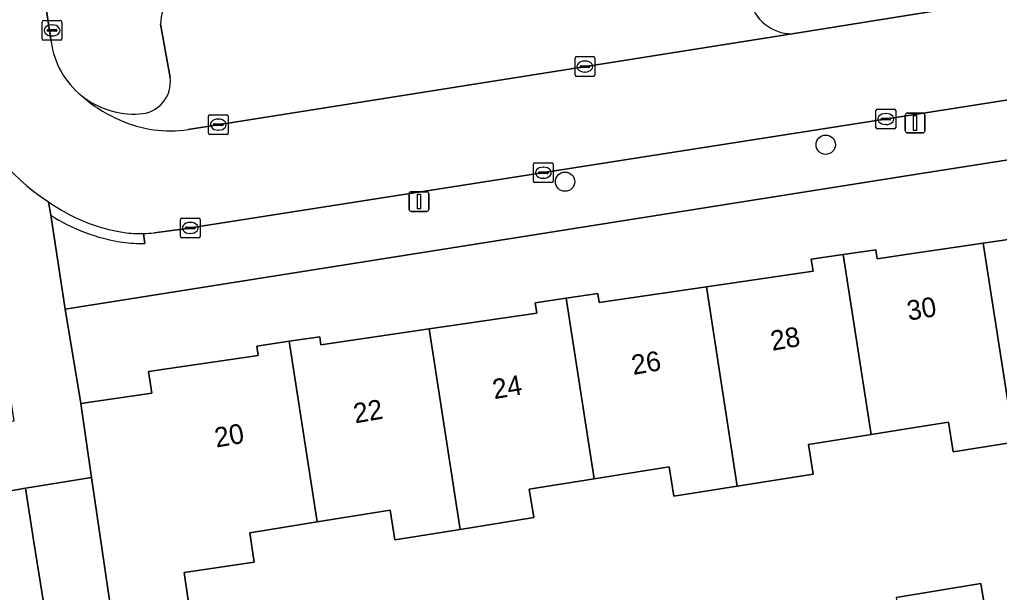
# Model space of a CAD drawing. Extents: x 160077 to 160948, y 386481 to 387498.
# Drawn here: x 160454.67 to 160504.27, y 387114.56 to 387143.58 of the extents above; entities that cross this region are included whole.
import ezdxf

# ---------------------------------------------------------------- set-up
doc = ezdxf.new("R2010")
doc.units = 0
for name, color, linetype in [('IMGEO_Boom', 7, 'Continuous'), ('IMGEO_Erf', 7, 'Continuous'), ('IMGEO_Kolk', 7, 'Continuous'), ('IMGEO_Lichtmast', 7, 'Continuous'), ('IMGEO_Muur', 7, 'Continuous'), ('IMGEO_Pand', 7, 'Continuous'), ('IMGEO_Pand_nummerreeks', 7, 'Continuous'), ('IMGEO_Parkeervlak_open', 7, 'Continuous'), ('IMGEO_Rijbaan_lokaal_open', 7, 'Continuous'), ('IMGEO_Voetpad_open', 7, 'Continuous')]:
    doc.layers.add(name, color=color, linetype=linetype)

msp = doc.modelspace()

# ---------------------------------------------------------------- linework, layer by layer
at = {"layer": 'IMGEO_Boom'}
for centre in [(160495.479, 387137.244), (160482.283, 387135.372)]:
    msp.add_circle(centre, 0.489, dxfattribs=at)
at = {"layer": 'IMGEO_Erf'}
for points in [[(160518.16, 387138.589), (160500, 387135.737), (160456.983, 387128.917), (160457.765, 387124.128), (160461.361, 387124.657), (160461.2, 387125.75), (160466.747, 387126.567), (160466.677, 387127.042), (160468.321, 387127.284), (160469.866, 387127.512), (160469.926, 387127.104), (160475.405, 387127.91), (160480.851, 387128.712), (160480.774, 387129.24), (160482.346, 387129.471), (160483.941, 387129.706), (160484.009, 387129.244), (160489.438, 387130.043), (160494.84, 387130.838), (160494.751, 387131.443), (160496.365, 387131.68), (160498.02, 387131.924), (160498.088, 387131.461), (160500, 387131.742), (160503.459, 387132.251), (160508.876, 387133.049)], [(160505.014, 387122.181), (160501.937, 387121.69), (160501.699, 387123.182), (160500, 387122.911), (160497.775, 387122.556), (160494.608, 387122.05), (160494.847, 387120.56), (160490.998, 387119.945), (160487.795, 387119.434), (160487.557, 387120.926), (160483.758, 387120.32), (160480.475, 387119.796), (160480.707, 387118.354), (160476.973, 387117.758), (160473.676, 387117.232), (160473.438, 387118.724), (160469.734, 387118.133), (160466.327, 387117.589), (160466.547, 387116.089), (160463.009, 387115.568), (160463.214, 387114.174)], [(160459.314, 387113.6), (160458.316, 387120.383), (160454.971, 387119.846), (160455.401, 387117.108), (160456.412, 387110.822)], [(160499.05, 387114.307), (160503.326, 387115.01), (160503.714, 387112.651)]]:
    msp.add_lwpolyline(points, dxfattribs=at)
at = {"layer": 'IMGEO_Kolk'}
for p, q in [((160455.816, 387142.609), (160455.816, 387143.461)), ((160455.891, 387143.535), (160456.743, 387143.535)), ((160456.817, 387143.461), (160456.817, 387142.609)), ((160456.075, 387143.029), (160456.075, 387143.041)), ((160456.513, 387142.992), (160456.115, 387142.992)), ((160456.118, 387143.078), (160456.516, 387143.078)), ((160456.304, 387143.315), (160456.329, 387143.315)), ((160456.559, 387143.041), (160456.559, 387143.029)), ((160456.743, 387142.535), (160455.891, 387142.535)), ((160456.327, 387142.755), (160456.302, 387142.755)), ((160482.789, 387140.78), (160482.789, 387141.632)), ((160482.864, 387141.706), (160483.716, 387141.706)), ((160483.277, 387141.486), (160483.302, 387141.486)), ((160483.79, 387141.632), (160483.79, 387140.78)), ((160483.048, 387141.2), (160483.048, 387141.212)), ((160483.486, 387141.163), (160483.088, 387141.163)), ((160483.091, 387141.249), (160483.489, 387141.249)), ((160483.3, 387140.926), (160483.275, 387140.926)), ((160483.532, 387141.212), (160483.532, 387141.2)), ((160483.716, 387140.706), (160482.864, 387140.706)), ((160498.024, 387138.121), (160498.024, 387138.973)), ((160498.099, 387139.047), (160498.951, 387139.047)), ((160499.025, 387138.973), (160499.025, 387138.121)), ((160464.231, 387137.838), (160464.231, 387138.69)), ((160464.306, 387138.764), (160465.158, 387138.764)), ((160464.719, 387138.544), (160464.744, 387138.544)), ((160465.232, 387138.69), (160465.232, 387137.838)), ((160498.283, 387138.541), (160498.283, 387138.553)), ((160498.721, 387138.504), (160498.323, 387138.504)), ((160498.326, 387138.59), (160498.724, 387138.59)), ((160498.512, 387138.827), (160498.537, 387138.827)), ((160498.767, 387138.553), (160498.767, 387138.541)), ((160464.49, 387138.258), (160464.49, 387138.27)), ((160464.928, 387138.221), (160464.53, 387138.221)), ((160464.533, 387138.307), (160464.931, 387138.307)), ((160464.742, 387137.984), (160464.717, 387137.984)), ((160464.974, 387138.27), (160464.974, 387138.258)), ((160498.951, 387138.047), (160498.099, 387138.047)), ((160498.535, 387138.267), (160498.51, 387138.267)), ((160465.158, 387137.764), (160464.306, 387137.764)), ((160480.685, 387135.4), (160480.685, 387136.252)), ((160480.76, 387136.326), (160481.612, 387136.326)), ((160481.173, 387136.106), (160481.198, 387136.106)), ((160481.686, 387136.252), (160481.686, 387135.4)), ((160480.944, 387135.82), (160480.944, 387135.832)), ((160481.382, 387135.783), (160480.984, 387135.783)), ((160480.987, 387135.869), (160481.385, 387135.869)), ((160481.196, 387135.546), (160481.171, 387135.546)), ((160481.428, 387135.832), (160481.428, 387135.82)), ((160481.612, 387135.326), (160480.76, 387135.326)), ((160462.886, 387133.528), (160463.738, 387133.528)), ((160462.811, 387132.602), (160462.811, 387133.454)), ((160463.07, 387133.022), (160463.07, 387133.034)), ((160463.508, 387132.985), (160463.11, 387132.985)), ((160463.113, 387133.071), (160463.511, 387133.071)), ((160463.299, 387133.308), (160463.324, 387133.308)), ((160463.554, 387133.034), (160463.554, 387133.022)), ((160463.812, 387133.454), (160463.812, 387132.602)), ((160463.738, 387132.528), (160462.886, 387132.528)), ((160463.322, 387132.748), (160463.297, 387132.748))]:
    msp.add_line(p, q, dxfattribs=at)
for points in [[(160455.816, 387142.609), (160455.816, 387143.461)], [(160455.891, 387143.535), (160456.743, 387143.535)], [(160456.817, 387143.461), (160456.817, 387142.609)], [(160456.743, 387142.535), (160455.891, 387142.535)], [(160482.789, 387140.78), (160482.789, 387141.632)], [(160482.864, 387141.706), (160483.716, 387141.706)], [(160483.79, 387141.632), (160483.79, 387140.78)], [(160483.716, 387140.706), (160482.864, 387140.706)], [(160498.024, 387138.121), (160498.024, 387138.973)], [(160498.099, 387139.047), (160498.951, 387139.047)], [(160499.025, 387138.973), (160499.025, 387138.121)], [(160464.231, 387137.838), (160464.231, 387138.69)], [(160464.306, 387138.764), (160465.158, 387138.764)], [(160465.232, 387138.69), (160465.232, 387137.838)], [(160498.951, 387138.047), (160498.099, 387138.047)], [(160465.158, 387137.764), (160464.306, 387137.764)], [(160480.685, 387135.4), (160480.685, 387136.252)], [(160480.76, 387136.326), (160481.612, 387136.326)], [(160481.686, 387136.252), (160481.686, 387135.4)], [(160481.612, 387135.326), (160480.76, 387135.326)], [(160462.886, 387133.528), (160463.738, 387133.528)], [(160462.811, 387132.602), (160462.811, 387133.454)], [(160463.812, 387133.454), (160463.812, 387132.602)], [(160463.738, 387132.528), (160462.886, 387132.528)]]:
    msp.add_lwpolyline(points, dxfattribs=at)
for centre, radius, start, end in [((160455.893, 387143.459), 0.0765, 91.552, 178.448), ((160455.893, 387143.459), 0.0765, 91.552, 178.448), ((160456.741, 387143.459), 0.0765, 1.552, 88.448), ((160456.741, 387143.459), 0.0765, 1.552, 88.448), ((160456.115, 387143.038), 0.0403, 85.8775, 175.7526), ((160456.112, 387143.028), 0.0366, 178.938, 274.7102), ((160456.516, 387143.035), 0.043, 264.8664, 352.4533), ((160456.52, 387143.04), 0.0386, 1.7309, 96.639), ((160455.893, 387142.611), 0.0765, 181.552, 268.448), ((160455.893, 387142.611), 0.0765, 181.552, 268.448), ((160456.741, 387142.611), 0.0765, 271.552, 358.448), ((160456.741, 387142.611), 0.0765, 271.552, 358.448), ((160482.866, 387141.63), 0.0765, 91.552, 178.448), ((160482.866, 387141.63), 0.0765, 91.552, 178.448), ((160483.714, 387141.63), 0.0765, 1.552, 88.448), ((160483.714, 387141.63), 0.0765, 1.552, 88.448), ((160483.088, 387141.209), 0.0403, 85.8775, 175.7526), ((160483.085, 387141.199), 0.0366, 178.938, 274.7102), ((160483.489, 387141.206), 0.043, 264.8664, 352.4533), ((160483.493, 387141.211), 0.0386, 1.7309, 96.639), ((160482.866, 387140.782), 0.0765, 181.552, 268.448), ((160482.866, 387140.782), 0.0765, 181.552, 268.448), ((160483.714, 387140.782), 0.0765, 271.552, 358.448), ((160483.714, 387140.782), 0.0765, 271.552, 358.448), ((160498.101, 387138.971), 0.0765, 91.552, 178.448), ((160498.101, 387138.971), 0.0765, 91.552, 178.448), ((160498.949, 387138.971), 0.0765, 1.552, 88.448), ((160498.949, 387138.971), 0.0765, 1.552, 88.448), ((160464.308, 387138.688), 0.0765, 91.552, 178.448), ((160464.308, 387138.688), 0.0765, 91.552, 178.448), ((160465.156, 387138.688), 0.0765, 1.552, 88.448), ((160465.156, 387138.688), 0.0765, 1.552, 88.448), ((160498.323, 387138.55), 0.0403, 85.8775, 175.7526), ((160498.32, 387138.54), 0.0366, 178.938, 274.7102), ((160498.724, 387138.547), 0.043, 264.8664, 352.4533), ((160498.728, 387138.552), 0.0386, 1.7309, 96.639), ((160464.53, 387138.267), 0.0403, 85.8775, 175.7526), ((160464.527, 387138.257), 0.0366, 178.938, 274.7102), ((160464.931, 387138.264), 0.043, 264.8664, 352.4533), ((160464.935, 387138.269), 0.0386, 1.7309, 96.639), ((160498.101, 387138.123), 0.0765, 181.552, 268.448), ((160498.101, 387138.123), 0.0765, 181.552, 268.448), ((160498.949, 387138.123), 0.0765, 271.552, 358.448), ((160498.949, 387138.123), 0.0765, 271.552, 358.448), ((160464.308, 387137.84), 0.0765, 181.552, 268.448), ((160464.308, 387137.84), 0.0765, 181.552, 268.448), ((160465.156, 387137.84), 0.0765, 271.552, 358.448), ((160465.156, 387137.84), 0.0765, 271.552, 358.448), ((160480.762, 387136.25), 0.0765, 91.552, 178.448), ((160480.762, 387136.25), 0.0765, 91.552, 178.448), ((160481.61, 387136.25), 0.0765, 1.552, 88.448), ((160481.61, 387136.25), 0.0765, 1.552, 88.448), ((160480.984, 387135.829), 0.0403, 85.8775, 175.7526), ((160480.981, 387135.819), 0.0366, 178.938, 274.7102), ((160481.385, 387135.826), 0.043, 264.8664, 352.4533), ((160481.389, 387135.831), 0.0386, 1.7309, 96.639), ((160480.762, 387135.402), 0.0765, 181.552, 268.448), ((160480.762, 387135.402), 0.0765, 181.552, 268.448), ((160481.61, 387135.402), 0.0765, 271.552, 358.448), ((160481.61, 387135.402), 0.0765, 271.552, 358.448), ((160462.888, 387133.452), 0.0765, 91.552, 178.448), ((160462.888, 387133.452), 0.0765, 91.552, 178.448), ((160463.736, 387133.452), 0.0765, 1.552, 88.448), ((160463.736, 387133.452), 0.0765, 1.552, 88.448), ((160463.11, 387133.031), 0.0403, 85.8775, 175.7526), ((160463.107, 387133.021), 0.0366, 178.938, 274.7102), ((160463.511, 387133.028), 0.043, 264.8664, 352.4533), ((160463.515, 387133.033), 0.0386, 1.7309, 96.639), ((160462.888, 387132.604), 0.0765, 181.552, 268.448), ((160462.888, 387132.604), 0.0765, 181.552, 268.448), ((160463.736, 387132.604), 0.0765, 271.552, 358.448), ((160463.736, 387132.604), 0.0765, 271.552, 358.448)]:
    msp.add_arc(centre, radius, start, end, dxfattribs=at)
for centre, major_axis, ratio, start_param, end_param in [((160456.303, 387143.035), (-0.387, 0.002), 0.722429, 4.712389, 7.853982), ((160456.328, 387143.035), (-0.39, 0.002), 0.717154, 1.570796, 4.712389), ((160483.276, 387141.206), (-0.387, 0.002), 0.722429, 4.712389, 7.853982), ((160483.301, 387141.206), (-0.39, 0.002), 0.717154, 1.570796, 4.712389), ((160464.718, 387138.264), (-0.387, 0.002), 0.722429, 4.712389, 7.853982), ((160464.743, 387138.264), (-0.39, 0.002), 0.717154, 1.570796, 4.712389), ((160498.511, 387138.547), (-0.387, 0.002), 0.722429, 4.712389, 7.853982), ((160498.536, 387138.547), (-0.39, 0.002), 0.717154, 1.570796, 4.712389), ((160481.172, 387135.826), (-0.387, 0.002), 0.722429, 4.712389, 7.853982), ((160481.197, 387135.826), (-0.39, 0.002), 0.717154, 1.570796, 4.712389), ((160463.298, 387133.028), (-0.387, 0.002), 0.722429, 4.712389, 7.853982), ((160463.323, 387133.028), (-0.39, 0.002), 0.717154, 1.570796, 4.712389)]:
    msp.add_ellipse(centre, major_axis=major_axis, ratio=ratio, start_param=start_param, end_param=end_param, dxfattribs=at)
at = {"layer": 'IMGEO_Lichtmast'}
for p, q in [((160499.509, 387137.945), (160499.509, 387138.745)), ((160499.509, 387138.745), (160499.509, 387137.945)), ((160499.609, 387138.845), (160500.399, 387138.845)), ((160500.399, 387138.845), (160499.609, 387138.845)), ((160500.499, 387138.745), (160500.499, 387137.945)), ((160500.499, 387137.945), (160500.499, 387138.745)), ((160500.399, 387137.845), (160499.609, 387137.845)), ((160499.609, 387137.845), (160500.399, 387137.845)), ((160474.393, 387133.963), (160474.393, 387134.763)), ((160474.393, 387134.763), (160474.393, 387133.963)), ((160474.493, 387134.863), (160475.283, 387134.863)), ((160475.283, 387134.863), (160474.493, 387134.863)), ((160475.383, 387134.763), (160475.383, 387133.963)), ((160475.383, 387133.963), (160475.383, 387134.763)), ((160475.283, 387133.863), (160474.493, 387133.863)), ((160474.493, 387133.863), (160475.283, 387133.863))]:
    msp.add_line(p, q, dxfattribs=at)
for points in [[(160499.929, 387138.72), (160500.079, 387138.72), (160500.079, 387137.97), (160499.929, 387137.97), (160499.929, 387138.72)], [(160474.813, 387134.738), (160474.963, 387134.738), (160474.963, 387133.988), (160474.813, 387133.988), (160474.813, 387134.738)]]:
    msp.add_lwpolyline(points, dxfattribs=at)
for centre, start, end in [((160499.609, 387138.745), 90, 180), ((160499.609, 387138.745), 90, 180), ((160500.399, 387138.745), 0, 90), ((160500.399, 387138.745), 360, 90), ((160499.609, 387137.945), 180, 270), ((160499.609, 387137.945), 180, 270), ((160500.399, 387137.945), 270, 0), ((160500.399, 387137.945), 270, 0), ((160474.493, 387134.763), 90, 180), ((160474.493, 387134.763), 90, 180), ((160475.283, 387134.763), 0, 90), ((160475.283, 387134.763), 360, 90), ((160474.493, 387133.963), 180, 270), ((160474.493, 387133.963), 180, 270), ((160475.283, 387133.963), 270, 0), ((160475.283, 387133.963), 270, 0)]:
    msp.add_arc(centre, 0.1, start, end, dxfattribs=at)
at = {"layer": 'IMGEO_Muur'}
for points in [[(160454.971, 387119.846), (160455.401, 387117.108)], [(160455.401, 387117.108), (160457.188, 387105.719)]]:
    msp.add_lwpolyline(points, dxfattribs=at)
at = {"layer": 'IMGEO_Pand'}
for points in [[(160510.391, 387133.864), (160508.791, 387133.629), (160508.876, 387133.049), (160503.459, 387132.251), (160505.014, 387122.181), (160508.988, 387122.816), (160508.757, 387124.257), (160511.8, 387124.743)], [(160497.775, 387122.556), (160500, 387122.911), (160501.699, 387123.182), (160501.937, 387121.69), (160505.014, 387122.181), (160503.459, 387132.251), (160500, 387131.742), (160498.088, 387131.461), (160498.02, 387131.924), (160496.365, 387131.68)], [(160496.365, 387131.68), (160494.751, 387131.443), (160494.84, 387130.838), (160489.438, 387130.043), (160490.998, 387119.945), (160494.847, 387120.56), (160494.608, 387122.05), (160497.775, 387122.556)], [(160483.758, 387120.32), (160487.557, 387120.926), (160487.795, 387119.434), (160490.998, 387119.945), (160489.438, 387130.043), (160484.009, 387129.244), (160483.941, 387129.706), (160482.346, 387129.471)], [(160482.346, 387129.471), (160480.774, 387129.24), (160480.851, 387128.712), (160475.405, 387127.91), (160476.973, 387117.758), (160480.707, 387118.354), (160480.475, 387119.796), (160483.758, 387120.32)], [(160469.734, 387118.133), (160473.438, 387118.724), (160473.676, 387117.232), (160476.973, 387117.758), (160475.405, 387127.91), (160469.926, 387127.104), (160469.866, 387127.512), (160468.321, 387127.284)], [(160458.316, 387120.383), (160459.314, 387113.6), (160463.214, 387114.174), (160463.009, 387115.568), (160466.547, 387116.089), (160466.327, 387117.589), (160469.734, 387118.133), (160468.321, 387127.284), (160466.677, 387127.042), (160466.747, 387126.567), (160461.2, 387125.75), (160461.361, 387124.657), (160457.765, 387124.128)], [(160503.714, 387112.651), (160503.326, 387115.01), (160499.05, 387114.307), (160499.415, 387111.944)]]:
    msp.add_lwpolyline(points, close=True, dxfattribs=at)
at = {"layer": 'IMGEO_Parkeervlak_open'}
for points in [[(160461.812, 387143.354), (160462.291, 387140.644)], [(160463.21, 387138.021), (160493.782, 387142.868)]]:
    msp.add_lwpolyline(points, dxfattribs=at)
for centre, radius, start, end in [((160463.806, 387143.357), 1.994, 101.9322, 180.0791), ((160493.751, 387144.998), 2.13, 190.1171, 270.8248), ((160460.693, 387140.42), 1.614, 271.355, 7.9685), ((160460.459, 387143.03), 4.232, 231.3319, 273.6828), ((160462.553, 387145.045), 7.124, 228.3092, 246.9428), ((160462.263, 387143.954), 6.008, 245.4057, 279.0655)]:
    msp.add_arc(centre, radius, start, end, dxfattribs=at)
at = {"layer": 'IMGEO_Rijbaan_lokaal_open'}
for points in [[(160456.269, 387142.466), (160452.642, 387166.52), (160451.698, 387172.524), (160451.124, 387176.171), (160448.647, 387191.915), (160447.856, 387196.313), (160447.484, 387198.268), (160447.442, 387198.531), (160447.437, 387198.56), (160442.512, 387197.622), (160444.978, 387182.595), (160446.013, 387176.282), (160447.401, 387167.413), (160448.319, 387161.471), (160449.654, 387152.837), (160450.551, 387147.034), (160451.402, 387141.525)], [(160551.502, 387151.942), (160527.693, 387148.256), (160525.948, 387147.982), (160522.624, 387147.455), (160518.297, 387146.776), (160500, 387143.854), (160493.782, 387142.868), (160463.21, 387138.021)], [(160461.484, 387132.784), (160462.906, 387132.966), (160489.417, 387137.116), (160500, 387138.779), (160517.735, 387141.567), (160517.975, 387141.6), (160534.205, 387144.195), (160534.212, 387144.165), (160560.487, 387148.307)]]:
    msp.add_lwpolyline(points, dxfattribs=at)
for centre, radius, start, end in [((160460.454, 387143.021), 4.222, 187.556, 231.3103), ((160461.962, 387143.341), 10.714, 198.1912, 237.0996), ((160462.553, 387145.045), 7.124, 228.3092, 246.9428), ((160462.263, 387143.954), 6.008, 245.4057, 279.0655), ((160461.321, 387141.648), 8.953, 234.6543, 261.2468), ((160460.777, 387138.613), 5.871, 261.9912, 271.5909), ((160460.826, 387138.018), 5.276, 271.242, 277.1687)]:
    msp.add_arc(centre, radius, start, end, dxfattribs=at)
at = {"layer": 'IMGEO_Voetpad_open'}
for points in [[(160449.437, 387203.261), (160446.676, 387201.618), (160446.779, 387201.233), (160447.259, 387199.514), (160447.334, 387199.112), (160447.437, 387198.56), (160447.442, 387198.531), (160447.484, 387198.268), (160447.856, 387196.313), (160448.647, 387191.915), (160451.124, 387176.171), (160451.618, 387176.247), (160452.192, 387172.6), (160451.698, 387172.524), (160452.642, 387166.52), (160456.269, 387142.466)], [(160493.782, 387142.868), (160500, 387143.854), (160518.297, 387146.776), (160522.624, 387147.455), (160522.443, 387148.54), (160522.567, 387148.56), (160522.517, 387148.875), (160522.023, 387148.799), (160519.378, 387148.285), (160516.768, 387147.865), (160501.448, 387145.45), (160500, 387145.329), (160493.933, 387144.411), (160493.093, 387149.407), (160492.562, 387152.579), (160492.554, 387152.587)], [(160462.291, 387140.644), (160461.812, 387143.354)], [(160517.975, 387141.6), (160517.735, 387141.567), (160500, 387138.779), (160489.417, 387137.116), (160462.906, 387132.966), (160461.484, 387132.784)], [(160451.783, 387139.996), (160452.121, 387137.644), (160450.991, 387137.444), (160451.773, 387132.109), (160453.032, 387132.259), (160454.373, 387123.247), (160453.264, 387123.077), (160453.744, 387119.63), (160454.971, 387119.846), (160458.316, 387120.383), (160457.765, 387124.128), (160456.983, 387128.917), (160456.246, 387133.673)], [(160456.246, 387133.673), (160456.983, 387128.917), (160500, 387135.737), (160518.16, 387138.589)], [(160456.246, 387133.673), (160456.142, 387134.345)], [(160456.142, 387134.345), (160456.246, 387133.673)], [(160461.02, 387132.246), (160460.94, 387132.744)], [(160460.94, 387132.744), (160461.02, 387132.246)], [(160457.484, 387103.826), (160457.248, 387105.64), (160456.412, 387110.822), (160455.401, 387117.108), (160454.971, 387119.846), (160453.744, 387119.63), (160451.862, 387119.314), (160452.082, 387117.899), (160452.281, 387116.619), (160453.551, 387108.448), (160454.011, 387105.484), (160458.14, 387078.907)]]:
    msp.add_lwpolyline(points, dxfattribs=at)
for centre, radius, start, end in [((160463.806, 387143.357), 1.994, 101.9322, 180.0791), ((160493.751, 387144.998), 2.13, 190.1171, 270.8248), ((160460.454, 387143.021), 4.222, 187.556, 231.3103), ((160460.693, 387140.42), 1.614, 271.355, 7.9685), ((160461.962, 387143.341), 10.714, 198.1912, 237.0996), ((160460.459, 387143.03), 4.232, 231.3319, 273.6828), ((160461.321, 387141.648), 8.953, 234.6543, 261.2468), ((160461.333, 387141.673), 9.48, 237.5462, 261.2002), ((160461.333, 387141.673), 9.48, 237.5462, 261.2002), ((160460.777, 387138.613), 5.871, 261.9912, 271.5909), ((160460.826, 387138.018), 5.276, 271.242, 277.1687), ((160460.779, 387138.7), 6.459, 262.0235, 272.1361), ((160460.779, 387138.7), 6.459, 262.0235, 272.1361)]:
    msp.add_arc(centre, radius, start, end, dxfattribs=at)

# ---------------------------------------------------------------- texts
at = {"layer": 'IMGEO_Pand_nummerreeks'}
for s, rotation, p in [('30', 9.2423, (160499.674, 387128.329)), ('28', 9.8875, (160492.778, 387126.803)), ('26', 9.8875, (160485.738, 387125.577)), ('24', 9.8875, (160478.702, 387124.35)), ('22', 9.8875, (160471.662, 387123.123)), ('20', 9.8875, (160464.631, 387121.897))]:
    msp.add_text(s, height=1, rotation=rotation, dxfattribs=at).set_placement(p)

doc.saveas('drawing.dxf')
